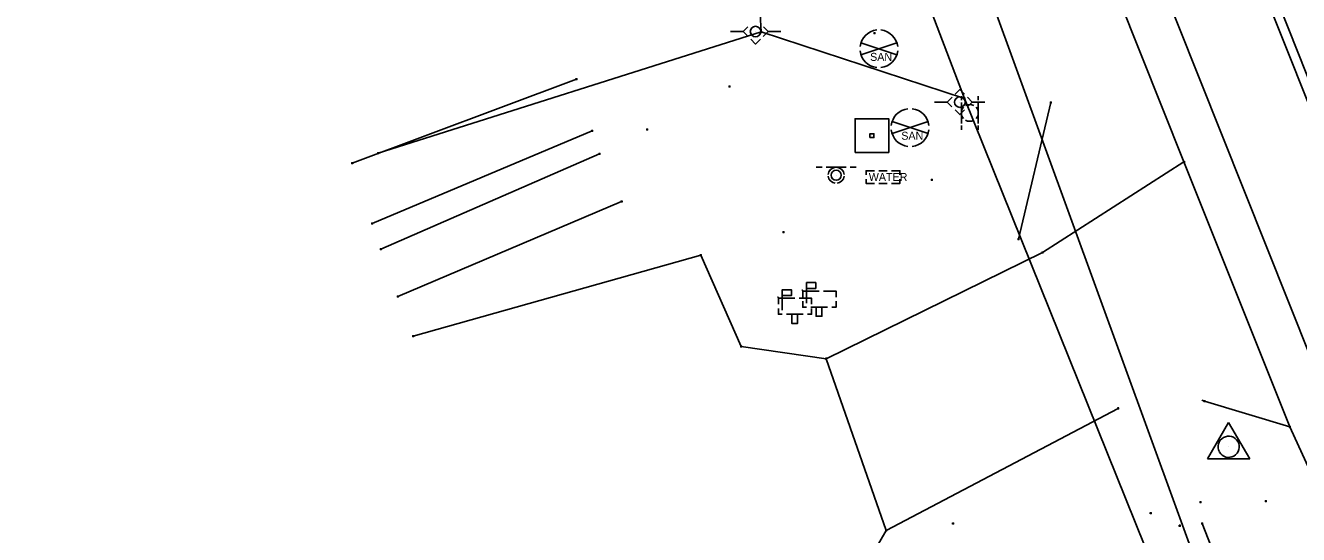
# Model space of a CAD drawing. Extents: x 1954856 to 2011933, y 399149 to 426294.
# Drawn here: x 2004586 to 2004737.1, y 408459.6 to 408520.1 of the extents above; entities that cross this region are included whole.
import ezdxf

# ---------------------------------------------------------------- set-up
doc = ezdxf.new("R2010")
doc.units = 0
for name, color, linetype in [('BankMent_ep', 7, 'Continuous'), ('BaselineSurvey', 7, 'Continuous'), ('DelineatorPost_ep', 7, 'Continuous'), ('Driveway_ep', 7, 'Continuous'), ('ElecAer_ep', 7, 'Continuous'), ('EndTreatMES_ep', 7, 'Continuous'), ('Mailbox_ep', 7, 'Continuous'), ('MeterWater_ep', 7, 'Continuous'), ('MonumentCC_ep', 7, 'Continuous'), ('MonumentIRC_ep', 7, 'Continuous'), ('PavtAsphalt_ep', 7, 'Continuous'), ('PavtAsphaltCrown_ep', 7, 'Continuous'), ('PipeCulvert_ep', 7, 'Continuous'), ('PointLocator_ep', 7, 'Continuous'), ('PoleShared_ep', 7, 'Continuous'), ('ShldrPaved_ep', 7, 'Continuous'), ('SignSingle_ep', 7, 'Continuous'), ('ValveCvrSewer_ep', 7, 'Continuous')]:
    doc.layers.add(name, color=color, linetype=linetype)

msp = doc.modelspace()

# ---------------------------------------------------------------- linework, layer by layer
at = {"layer": 'BankMent_ep'}
for p, q in [((2004651.38, 408513.7), (2004624.78, 408503.72)), ((2004630.19, 408487.88), (2004656.75, 408499.17))]:
    msp.add_line(p, q, dxfattribs=at)
for points in [[(2004627.12, 408496.56), (2004653.26, 408507.56)], [(2004654.12, 408504.83), (2004628.17, 408493.52)]]:
    msp.add_lwpolyline(points, dxfattribs=at)
at = {"layer": 'BaselineSurvey'}
msp.add_line((2004967.71, 407935.04), (2004043.6, 410254.04), dxfattribs=at)
msp.add_line((2004967.71, 407935.04), (2004043.6, 410254.04), dxfattribs=at)
at = {"layer": 'DelineatorPost_ep'}
for p, q in [((2004697.08, 408511.7), (2004697.08, 408511.2)), ((2004697.08, 408508.45), (2004697.08, 408510.95)), ((2004699.08, 408511.7), (2004699.08, 408511.2)), ((2004699.08, 408510.95), (2004699.08, 408508.45)), ((2004698.08, 408509.7), (2004698.08, 408509.7)), ((2004697.08, 408508.2), (2004697.08, 408507.7)), ((2004699.08, 408508.2), (2004699.08, 408507.7))]:
    msp.add_line(p, q, dxfattribs=at)
for start, end in [(60, 120), (138.5904, 221.4096), (318.5904, 41.4096), (240, 300)]:
    msp.add_arc((2004698.08, 408509.7), 1, start, end, dxfattribs=at)
at = {"layer": 'Driveway_ep'}
for p, q in [((2004703.88, 408494.7), (2004707.72, 408510.94)), ((2004706.71, 408493.11), (2004723.51, 408503.89)), ((2004631.99, 408483.17), (2004666.15, 408492.8)), ((2004666.15, 408492.8), (2004670.94, 408481.95)), ((2004681.04, 408480.49), (2004706.71, 408493.11)), ((2004670.94, 408481.95), (2004681.04, 408480.49)), ((2004688.16, 408460.08), (2004681.04, 408480.49)), ((2004715.69, 408474.59), (2004688.16, 408460.08)), ((2004725.96, 408475.45), (2004725.63, 408475.55)), ((2004736.07, 408472.39), (2004725.96, 408475.45))]:
    msp.add_line(p, q, dxfattribs=at)
msp.add_lwpolyline([(2004688.16, 408460.08), (2004676.95, 408440.62), (2004707.33, 408361.89), (2004675.89, 408345.91)], dxfattribs=at)
at = {"layer": 'ElecAer_ep'}
for points in [[(2004673.32, 408519.34), (2004669.71, 408584.23), (2004697.45, 408511.41)], [(2004811.27, 408223.79), (2004783.16, 408298.48), (2004697.45, 408511.41), (2004673.32, 408519.34), (2004627.85, 408504.91)]]:
    msp.add_lwpolyline(points, dxfattribs=at)
at = {"layer": 'EndTreatMES_ep'}
msp.add_line((2004725.67, 408460.92), (2004729.05, 408452.3), dxfattribs=at)
at = {"layer": 'Mailbox_ep'}
for p, q in [((2004678.25, 408488.52), (2004678.25, 408487.82)), ((2004680.2, 408488.52), (2004678.25, 408488.52)), ((2004678.71, 408487.11), (2004678.71, 408488.84)), ((2004678.71, 408488.84), (2004679.7, 408488.84)), ((2004682.2, 408488.52), (2004682.2, 408487.82)), ((2004675.36, 408487.68), (2004675.36, 408486.97)), ((2004677.31, 408487.68), (2004675.36, 408487.68)), ((2004675.82, 408486.26), (2004675.82, 408488)), ((2004675.82, 408488), (2004676.81, 408488)), ((2004679.2, 408486.61), (2004679.7, 408486.61)), ((2004679.31, 408487.68), (2004679.31, 408486.97)), ((2004679.7, 408486.61), (2004681.2, 408486.61)), ((2004682.2, 408487.32), (2004682.2, 408486.61)), ((2004676.31, 408485.77), (2004676.81, 408485.77)), ((2004676.81, 408485.77), (2004678.31, 408485.77)), ((2004679.31, 408486.47), (2004679.31, 408485.77)), ((2004680.18, 408485.54), (2004680.18, 408485.54)), ((2004677.3, 408484.69), (2004677.3, 408484.69))]:
    msp.add_line(p, q, dxfattribs=at)
for points in [[(2004679.7, 408489.54), (2004678.71, 408489.54), (2004678.71, 408488.84)], [(2004679.7, 408488.84), (2004679.79, 408488.84), (2004679.79, 408489.54), (2004679.7, 408489.54)], [(2004676.81, 408488.69), (2004675.82, 408488.69), (2004675.82, 408488)], [(2004676.81, 408488), (2004676.9, 408488), (2004676.9, 408488.69), (2004676.81, 408488.69)], [(2004678.13, 408488.65), (2004678.21, 408488.65), (2004678.25, 408488.48)], [(2004682.2, 408488.07), (2004682.2, 408488.52), (2004680.7, 408488.52)], [(2004675.25, 408487.81), (2004675.33, 408487.81), (2004675.36, 408487.63)], [(2004679.31, 408487.22), (2004679.31, 408487.68), (2004677.81, 408487.68)], [(2004678.25, 408487.32), (2004678.25, 408486.61), (2004678.7, 408486.61)], [(2004679.84, 408486.61), (2004679.84, 408485.54), (2004680.53, 408485.54), (2004680.53, 408486.61)], [(2004681.7, 408486.61), (2004682.2, 408486.61), (2004682.2, 408487.07)], [(2004675.36, 408486.47), (2004675.36, 408485.77), (2004675.81, 408485.77)], [(2004676.95, 408485.77), (2004676.95, 408484.69), (2004677.64, 408484.69), (2004677.64, 408485.77)], [(2004678.81, 408485.77), (2004679.31, 408485.77), (2004679.31, 408486.22)]]:
    msp.add_lwpolyline(points, dxfattribs=at)
at = {"layer": 'MeterWater_ep'}
msp.add_line((2004687.78, 408502.08), (2004687.78, 408502.08), dxfattribs=at)
for points in [[(2004685.78, 408502.33), (2004685.78, 408502.83), (2004686.78, 408502.83)], [(2004686.78, 408501.33), (2004685.78, 408501.33), (2004685.78, 408501.83)], [(2004687.28, 408502.83), (2004688.28, 408502.83)], [(2004688.78, 408502.83), (2004689.78, 408502.83), (2004689.78, 408502.33)], [(2004689.78, 408501.83), (2004689.78, 408501.33), (2004688.78, 408501.33)], [(2004688.28, 408501.33), (2004687.28, 408501.33)]]:
    msp.add_lwpolyline(points, dxfattribs=at)
at = {"layer": 'MonumentCC_ep'}
msp.add_line((2004686.46, 408507), (2004686.46, 408507), dxfattribs=at)
msp.add_lwpolyline([(2004684.46, 408505), (2004688.47, 408505), (2004688.47, 408509), (2004684.46, 408509), (2004684.46, 408505)], dxfattribs=at)
msp.add_lwpolyline([(2004686.23, 408506.76), (2004686.23, 408507.23), (2004686.7, 408507.23), (2004686.7, 408506.76)], close=True, dxfattribs=at)
at = {"layer": 'MonumentIRC_ep'}
for p, q in [((2004726.31, 408468.58), (2004728.81, 408472.91)), ((2004728.81, 408472.91), (2004731.31, 408468.58)), ((2004728.81, 408470.03), (2004728.81, 408470.03)), ((2004726.31, 408468.58), (2004731.31, 408468.58))]:
    msp.add_line(p, q, dxfattribs=at)
msp.add_arc((2004728.81, 408470.03), 1.26, 209.9294, 209.03, dxfattribs=at)
at = {"layer": 'PavtAsphalt_ep'}
msp.add_lwpolyline([(2004908.03, 408056.32), (2004870.87, 408148.95), (2004833.86, 408242.04), (2004796.66, 408334.54), (2004759.71, 408427.58), (2004722.75, 408520.32), (2004685.7, 408613.32), (2004648.57, 408706.42), (2004611.45, 408799.43), (2004574.35, 408892.33), (2004537.27, 408984.58), (2004500.45, 409078.03), (2004463.69, 409171), (2004426.25, 409264.13), (2004389.64, 409356.86), (2004352.63, 409449.56), (2004314.97, 409542.01), (2004278.21, 409635.44)], dxfattribs=at)
at = {"layer": 'PavtAsphaltCrown_ep'}
msp.add_lwpolyline([(2004919.3, 408060.52), (2004882.31, 408153.48), (2004845.12, 408246.24), (2004807.96, 408339.12), (2004770.74, 408431.91), (2004733.82, 408525.03), (2004696.73, 408617.52), (2004659.9, 408710.76), (2004622.5, 408803.47), (2004585.74, 408896.22), (2004548.97, 408989.35), (2004511.74, 409082.34), (2004474.91, 409175.32), (2004437.75, 409268.1), (2004401.04, 409361.08), (2004363.75, 409453.88), (2004326.65, 409546.7), (2004289.56, 409639.69)], dxfattribs=at)
at = {"layer": 'PipeCulvert_ep'}
msp.add_lwpolyline([(2004725.66, 408454.29), (2004650.81, 408660.16)], dxfattribs=at)
at = {"layer": 'PointLocator_ep'}
for p, q in [((2004673.45, 408519.34), (2004673.2, 408519.34)), ((2004673.32, 408519.22), (2004673.32, 408519.47)), ((2004673.32, 408519.34), (2004673.32, 408519.34)), ((2004686.89, 408519.17), (2004686.64, 408519.17)), ((2004686.77, 408519.05), (2004686.77, 408519.3)), ((2004686.77, 408519.17), (2004686.77, 408519.17)), ((2004651.5, 408513.7), (2004651.25, 408513.7)), ((2004651.38, 408513.58), (2004651.38, 408513.83)), ((2004651.38, 408513.7), (2004651.38, 408513.7)), ((2004669.67, 408512.83), (2004669.42, 408512.83)), ((2004669.55, 408512.7), (2004669.55, 408512.95)), ((2004669.55, 408512.83), (2004669.55, 408512.83)), ((2004697.57, 408511.41), (2004697.32, 408511.41)), ((2004697.45, 408511.28), (2004697.45, 408511.53)), ((2004697.45, 408511.41), (2004697.45, 408511.41)), ((2004707.84, 408510.94), (2004707.59, 408510.94)), ((2004707.72, 408510.81), (2004707.72, 408511.06)), ((2004707.72, 408510.94), (2004707.72, 408510.94)), ((2004653.26, 408507.44), (2004653.26, 408507.69)), ((2004659.92, 408507.73), (2004659.67, 408507.73)), ((2004659.8, 408507.6), (2004659.8, 408507.85)), ((2004659.8, 408507.73), (2004659.8, 408507.73)), ((2004653.38, 408507.56), (2004653.13, 408507.56)), ((2004653.26, 408507.56), (2004653.26, 408507.56)), ((2004627.98, 408504.91), (2004627.73, 408504.91)), ((2004627.85, 408504.78), (2004627.85, 408505.03)), ((2004627.85, 408504.91), (2004627.85, 408504.91)), ((2004654.24, 408504.83), (2004653.99, 408504.83)), ((2004654.12, 408504.71), (2004654.12, 408504.96)), ((2004654.12, 408504.83), (2004654.12, 408504.83)), ((2004624.91, 408503.72), (2004624.66, 408503.72)), ((2004624.78, 408503.59), (2004624.78, 408503.84)), ((2004624.78, 408503.72), (2004624.78, 408503.72)), ((2004723.64, 408503.89), (2004723.39, 408503.89)), ((2004723.51, 408503.77), (2004723.51, 408504.02)), ((2004723.51, 408503.89), (2004723.51, 408503.89)), ((2004693.69, 408501.75), (2004693.44, 408501.75)), ((2004693.56, 408501.63), (2004693.56, 408501.88)), ((2004693.56, 408501.75), (2004693.56, 408501.75)), ((2004656.88, 408499.17), (2004656.63, 408499.17)), ((2004656.75, 408499.04), (2004656.75, 408499.29)), ((2004656.75, 408499.17), (2004656.75, 408499.17)), ((2004627.25, 408496.56), (2004627, 408496.56)), ((2004627.12, 408496.43), (2004627.12, 408496.68)), ((2004627.12, 408496.56), (2004627.12, 408496.56)), ((2004675.97, 408495.41), (2004675.97, 408495.66)), ((2004676.09, 408495.54), (2004675.84, 408495.54)), ((2004675.97, 408495.54), (2004675.97, 408495.54)), ((2004704, 408494.7), (2004703.75, 408494.7)), ((2004703.88, 408494.57), (2004703.88, 408494.82)), ((2004703.88, 408494.7), (2004703.88, 408494.7)), ((2004628.29, 408493.52), (2004628.04, 408493.52)), ((2004628.17, 408493.39), (2004628.17, 408493.64)), ((2004628.17, 408493.52), (2004628.17, 408493.52)), ((2004666.28, 408492.8), (2004666.03, 408492.8)), ((2004666.15, 408492.68), (2004666.15, 408492.93)), ((2004666.15, 408492.8), (2004666.15, 408492.8)), ((2004706.83, 408493.11), (2004706.58, 408493.11)), ((2004706.71, 408492.98), (2004706.71, 408493.23)), ((2004706.71, 408493.11), (2004706.71, 408493.11)), ((2004630.32, 408487.88), (2004630.07, 408487.88)), ((2004630.19, 408487.76), (2004630.19, 408488.01)), ((2004630.19, 408487.88), (2004630.19, 408487.88)), ((2004632.12, 408483.17), (2004631.87, 408483.17)), ((2004631.99, 408483.04), (2004631.99, 408483.29)), ((2004631.99, 408483.17), (2004631.99, 408483.17)), ((2004670.94, 408481.83), (2004670.94, 408482.08)), ((2004671.07, 408481.95), (2004670.82, 408481.95)), ((2004670.94, 408481.95), (2004670.94, 408481.95)), ((2004681.17, 408480.49), (2004680.92, 408480.49)), ((2004681.04, 408480.37), (2004681.04, 408480.62)), ((2004681.04, 408480.49), (2004681.04, 408480.49)), ((2004715.81, 408474.59), (2004715.56, 408474.59)), ((2004715.69, 408474.47), (2004715.69, 408474.72)), ((2004715.69, 408474.59), (2004715.69, 408474.59)), ((2004726.08, 408475.45), (2004725.83, 408475.45)), ((2004725.96, 408475.33), (2004725.96, 408475.58)), ((2004725.96, 408475.45), (2004725.96, 408475.45)), ((2004736.19, 408472.39), (2004735.94, 408472.39)), ((2004736.07, 408472.27), (2004736.07, 408472.52)), ((2004736.07, 408472.39), (2004736.07, 408472.39)), ((2004725.59, 408463.45), (2004725.34, 408463.45)), ((2004725.47, 408463.32), (2004725.47, 408463.57)), ((2004725.47, 408463.45), (2004725.47, 408463.45)), ((2004733.35, 408463.57), (2004733.1, 408463.57)), ((2004733.22, 408463.44), (2004733.22, 408463.69)), ((2004733.22, 408463.57), (2004733.22, 408463.57)), ((2004696.22, 408460.9), (2004695.97, 408460.9)), ((2004696.09, 408460.78), (2004696.09, 408461.03)), ((2004696.09, 408460.9), (2004696.09, 408460.9)), ((2004719.68, 408462.16), (2004719.43, 408462.16)), ((2004719.56, 408462.03), (2004719.56, 408462.28)), ((2004719.56, 408462.16), (2004719.56, 408462.16)), ((2004725.79, 408460.92), (2004725.54, 408460.92)), ((2004725.67, 408460.8), (2004725.67, 408461.05)), ((2004725.67, 408460.92), (2004725.67, 408460.92)), ((2004688.28, 408460.08), (2004688.03, 408460.08)), ((2004688.16, 408459.95), (2004688.16, 408460.2)), ((2004688.16, 408460.08), (2004688.16, 408460.08)), ((2004723.12, 408460.65), (2004722.87, 408460.65)), ((2004723, 408460.53), (2004723, 408460.78)), ((2004723, 408460.65), (2004723, 408460.65))]:
    msp.add_line(p, q, dxfattribs=at)
at = {"layer": 'PoleShared_ep'}
for p, q in [((2004671.17, 408519.36), (2004671.73, 408519.93)), ((2004669.67, 408519.36), (2004671.17, 408519.36)), ((2004671.73, 408518.8), (2004671.17, 408519.36)), ((2004672.65, 408519.36), (2004672.65, 408519.36)), ((2004675.64, 408519.36), (2004674.14, 408519.36)), ((2004693.91, 408510.98), (2004695.41, 408510.98)), ((2004695.41, 408510.98), (2004695.98, 408511.55)), ((2004695.97, 408510.42), (2004695.41, 408510.98)), ((2004696.9, 408510.98), (2004696.9, 408510.98)), ((2004699.88, 408510.98), (2004698.38, 408510.98))]:
    msp.add_line(p, q, dxfattribs=at)
for points in [[(2004673.58, 408519.93), (2004674.14, 408519.36), (2004673.57, 408518.79)], [(2004673.22, 408518.44), (2004672.65, 408517.87), (2004672.09, 408518.44)], [(2004696.33, 408511.91), (2004696.9, 408512.47), (2004697.46, 408511.91)], [(2004697.82, 408511.55), (2004698.38, 408510.98), (2004697.82, 408510.42)], [(2004697.46, 408510.06), (2004696.9, 408509.5), (2004696.33, 408510.06)]]:
    msp.add_lwpolyline(points, dxfattribs=at)
for centre, start, end in [((2004672.65, 408519.36), 90, 270), ((2004672.65, 408519.36), 270, 90), ((2004696.9, 408510.98), 90, 270), ((2004696.9, 408510.98), 270, 90)]:
    msp.add_arc(centre, 0.625, start, end, dxfattribs=at)
at = {"layer": 'ShldrPaved_ep'}
msp.add_lwpolyline([(2004903.29, 408054.42), (2004866.25, 408147.18), (2004829.78, 408238.43), (2004819.43, 408264.53), (2004792.12, 408332.81), (2004764.06, 408411.25), (2004736.07, 408472.39), (2004723.51, 408503.89), (2004692.56, 408581.58), (2004685.95, 408598.81), (2004662.72, 408655.96), (2004643.53, 408704.54), (2004611.46, 408784.57), (2004586.66, 408847.41), (2004569.7, 408890.52), (2004561.67, 408910.22), (2004521.28, 409011.51), (2004496.04, 409076.36), (2004458.97, 409168.82), (2004421.59, 409262.3), (2004384.82, 409355.23), (2004347.84, 409447.99), (2004310.72, 409540.77), (2004273.84, 409633.55)], dxfattribs=at)
at = {"layer": 'SignSingle_ep'}
for p, q in [((2004679.84, 408503.24), (2004680.54, 408503.24)), ((2004681.04, 408503.24), (2004683.39, 408503.24)), ((2004683.89, 408503.24), (2004684.59, 408503.24)), ((2004682.22, 408502.29), (2004682.22, 408502.29))]:
    msp.add_line(p, q, dxfattribs=at)
msp.add_circle((2004682.22, 408502.29), 0.594, dxfattribs=at)
for start, end in [(96.0423, 173.9577), (6.0423, 83.9577), (186.0423, 263.9577), (276.0423, 353.9577)]:
    msp.add_arc((2004682.22, 408502.29), 0.95, start, end, dxfattribs=at)
at = {"layer": 'ValveCvrSewer_ep'}
for p, q in [((2004685.16, 408516.61), (2004689.43, 408518.03)), ((2004689.43, 408516.61), (2004685.16, 408518.03)), ((2004687.29, 408517.32), (2004687.29, 408517.32)), ((2004688.86, 408507.24), (2004693.13, 408508.66)), ((2004693.13, 408507.24), (2004688.86, 408508.66)), ((2004690.99, 408507.95), (2004690.99, 408507.95))]:
    msp.add_line(p, q, dxfattribs=at)
for centre, start, end in [((2004687.29, 408517.32), 96.3794, 173.6206), ((2004687.29, 408517.32), 6.3794, 83.6206), ((2004687.29, 408517.32), 186.3794, 263.6206), ((2004687.29, 408517.32), 276.3794, 353.6206), ((2004690.99, 408507.95), 96.3794, 173.6206), ((2004690.99, 408507.95), 6.3794, 83.6206), ((2004690.99, 408507.95), 186.3794, 263.6206), ((2004690.99, 408507.95), 276.3794, 353.6206)]:
    msp.add_arc(centre, 2.25, start, end, dxfattribs=at)

# ---------------------------------------------------------------- texts
at = {"layer": 'MeterWater_ep'}
msp.add_text('WATER', height=0.95, dxfattribs=at).set_placement((2004686.09, 408501.61))
at = {"layer": 'ValveCvrSewer_ep'}
for p in [(2004686.25, 408515.88), (2004689.95, 408506.51)]:
    msp.add_text('SAN', height=0.95, dxfattribs=at).set_placement(p)

doc.saveas('drawing.dxf')
